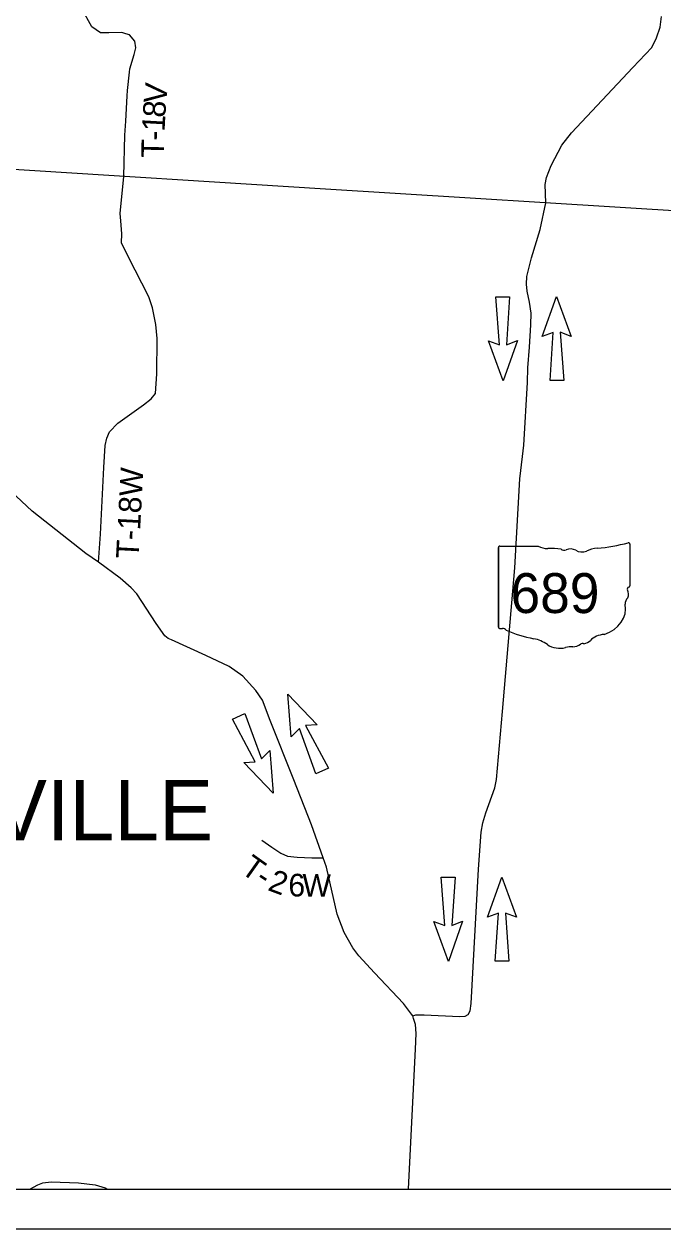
# Model space of a CAD drawing. Extents: x -15 to 405, y -40 to 87.
# Drawn here: x 25.513 to 27.116, y -34.096 to -31.075 of the extents above; entities that cross this region are included whole.
import ezdxf

# ---------------------------------------------------------------- set-up
doc = ezdxf.new("R2010")
doc.units = 0
for name, color, linetype in [('GM_P_State_Location', 7, 'Continuous'), ('GM_X_County_Road_Text', 7, 'Continuous'), ('GM_X_Minor_River', 7, 'Continuous'), ('GM_X_Rail_Line', 7, 'Continuous'), ('GM_X_State_Location', 7, 'Continuous'), ('GM_X_Township', 7, 'Continuous'), ('GM_X_Township_Subdivision', 7, 'Continuous')]:
    doc.layers.add(name, color=color, linetype=linetype)

msp = doc.modelspace()

# ---------------------------------------------------------------- linework, layer by layer
at = {"layer": 'GM_P_State_Location'}
for points in [[(25.7638, -31.4568), (25.7658, -31.3529), (25.7684, -31.3178), (25.7716, -31.2542), (25.7723, -31.2412), (25.7778, -31.195), (25.7789, -31.187), (25.7892, -31.1506), (25.7935, -31.1345), (25.7911, -31.1177), (25.778, -31.102), (25.7681, -31.0988), (25.7586, -31.096), (25.7262, -31.0966), (25.7052, -31.0963), (25.6835, -31.0815), (25.6574, -31.035)], [(25.7, -32.4234), (25.705, -32.3535), (25.7134, -32.1861), (25.7168, -32.1311), (25.7206, -32.1125), (25.7278, -32.0973), (25.7487, -32.0753), (25.8124, -32.0291), (25.8318, -32.0139), (25.8431, -32.0011), (25.8466, -31.9513), (25.8474, -31.8629), (25.844, -31.828), (25.8353, -31.7859), (25.8266, -31.7589), (25.7747, -31.6576), (25.7577, -31.623), (25.7581, -31.6003), (25.7558, -31.5676), (25.7539, -31.5494), (25.7638, -31.4568)], [(26.1098, -33.1211), (26.1352, -33.1382), (26.1575, -33.1534), (26.1738, -33.161), (26.1981, -33.1637), (26.2352, -33.1648), (26.2633, -33.1649)]]:
    msp.add_lwpolyline(points, dxfattribs=at)
at = {"layer": 'GM_X_Rail_Line'}
for p, q in [((26.2696, -31.4887), (24.8032, -31.3963)), ((27.2876, -31.5517), (26.2696, -31.4887))]:
    msp.add_line(p, q, dxfattribs=at)
at = {"layer": 'GM_X_State_Location'}
for p, q in [((26.697, -31.7584), (26.7314, -31.7581)), ((26.7062, -31.8792), (26.697, -31.7584)), ((26.7314, -31.7581), (26.7236, -31.8791)), ((26.8135, -31.8582), (26.8489, -31.7573)), ((26.8489, -31.7573), (26.8858, -31.8578)), ((26.7155, -31.9693), (26.6788, -31.8688)), ((26.6788, -31.8688), (26.7062, -31.8792)), ((26.751, -31.8684), (26.7155, -31.9693)), ((26.7236, -31.8791), (26.751, -31.8684)), ((26.841, -31.8476), (26.8135, -31.8582)), ((26.8331, -31.9685), (26.841, -31.8476)), ((26.8858, -31.8578), (26.8583, -31.8474)), ((26.8583, -31.8474), (26.8676, -31.9682)), ((26.8676, -31.9682), (26.8331, -31.9685)), ((26.1746, -32.7549), (26.249, -32.8319)), ((26.183, -32.8615), (26.1746, -32.7549)), ((26.0361, -32.8174), (26.0675, -32.8032)), ((26.0675, -32.8032), (26.1093, -32.917)), ((26.0934, -32.9241), (26.0361, -32.8174)), ((26.249, -32.8319), (26.2197, -32.8336)), ((26.2197, -32.8336), (26.277, -32.9403)), ((26.2039, -32.8407), (26.183, -32.8615)), ((26.2456, -32.9545), (26.2039, -32.8407)), ((26.1093, -32.917), (26.13, -32.8962)), ((26.13, -32.8962), (26.1383, -33.0028)), ((26.0642, -32.9257), (26.0934, -32.9241)), ((26.1383, -33.0028), (26.0642, -32.9257)), ((26.277, -32.9403), (26.2456, -32.9545)), ((26.5601, -33.214), (26.5945, -33.2139)), ((26.5688, -33.3348), (26.5601, -33.214)), ((26.5945, -33.2139), (26.5863, -33.3349)), ((26.6762, -33.3142), (26.712, -33.2135)), ((26.712, -33.2135), (26.7485, -33.3141)), ((26.7037, -33.3037), (26.6762, -33.3142)), ((26.6954, -33.4246), (26.7037, -33.3037)), ((26.7485, -33.3141), (26.7211, -33.3036)), ((26.7211, -33.3036), (26.7299, -33.4245)), ((26.5778, -33.425), (26.5415, -33.3244)), ((26.5415, -33.3244), (26.5688, -33.3348)), ((26.6137, -33.3242), (26.5778, -33.425)), ((26.5863, -33.3349), (26.6137, -33.3242)), ((26.7299, -33.4245), (26.6954, -33.4246)), ((26.4776, -33.9955), (26.4777, -33.9948))]:
    msp.add_line(p, q, dxfattribs=at)
for points in [[(26.4889, -33.5616), (26.4958, -33.559), (26.5174, -33.559), (26.6059, -33.563), (26.6203, -33.5624), (26.6276, -33.5583), (26.6326, -33.5489), (26.6348, -33.5303), (26.6535, -33.1937), (26.6598, -33.1011), (26.6643, -33.0776), (26.6719, -33.0523), (26.6948, -32.9892), (26.6989, -32.9684), (26.7136, -32.7984), (26.7447, -32.4384), (26.7575, -32.2149), (26.7641, -32.1587), (26.7668, -32.1303), (26.7767, -31.9735), (26.7776, -31.9363), (26.7814, -31.8851), (26.7849, -31.8289), (26.7857, -31.7993), (26.7812, -31.7715), (26.7755, -31.7441), (26.7735, -31.727), (26.7745, -31.7072), (26.7866, -31.6611), (26.8085, -31.5896), (26.8228, -31.5229), (26.8205, -31.4766), (26.8237, -31.4592), (26.836, -31.429), (26.8625, -31.3785), (26.8865, -31.3473), (27.0404, -31.1836), (27.0883, -31.1334), (27.1004, -31.1089), (27.1095, -31.0821), (27.113, -31.0559)], [(26.4889, -33.5616), (26.4856, -33.5573), (26.4651, -33.5304), (26.3922, -33.4538), (26.3533, -33.4106), (26.338, -33.391), (26.3166, -33.3527), (26.2991, -33.3061), (26.2716, -33.1887), (26.2633, -33.1649), (26.2344, -33.0822), (26.1897, -32.9698), (26.1308, -32.8204), (26.1114, -32.7696), (26.0951, -32.7454), (26.0622, -32.7096), (26.028, -32.6851), (25.9692, -32.6577), (25.8832, -32.6187), (25.8745, -32.6148), (25.8666, -32.6082), (25.8443, -32.5775), (25.796, -32.5035), (25.7822, -32.4884), (25.7545, -32.4637), (25.7, -32.4234), (25.6684, -32.402), (25.5337, -32.2959), (25.4801, -32.2457)], [(26.4777, -33.9948), (26.4953, -33.6452), (26.497, -33.6054), (26.4951, -33.5826), (26.4907, -33.5681), (26.4889, -33.5616)], [(25.5276, -33.9955), (25.5474, -33.9853), (25.5601, -33.9802), (25.5814, -33.9771), (25.65, -33.98), (25.6917, -33.9852), (25.7163, -33.9928), (25.7223, -33.9955)]]:
    msp.add_lwpolyline(points, dxfattribs=at)
at = {"layer": 'GM_X_Township'}
for p, q in [((23.1652, -33.9955), (29.9652, -33.9955)), ((23.0652, -34.0955), (30.0652, -34.0955))]:
    msp.add_line(p, q, dxfattribs=at)
at = {"layer": 'GM_X_Township_Subdivision'}
for p, q in [((27.0331, -32.3785), (27.0331, -32.4832)), ((26.7035, -32.3869), (26.7035, -32.587)), ((26.7035, -32.587), (26.7035, -32.3869)), ((26.7035, -32.587), (26.7035, -32.3869)), ((26.7068, -32.3834), (26.8033, -32.3834)), ((27.0331, -32.4831), (27.0331, -32.4832))]:
    msp.add_line(p, q, dxfattribs=at)
for centre, major_axis, start_param, end_param in [((26.9157, -32.1106), (0.3495, 0), 4.814394, 5.042369), ((27.0295, -32.378), (0.00367, 0), 6.141152, 7.989035), ((26.7073, -32.3865), (0.00382, 0), 1.712693, 3.28349), ((26.8263, -32.3602), (0.037, 0), 4.042523, 4.731795), ((26.8386, -32.4958), (0.133, 0), 1.404758, 1.657858), ((26.8687, -32.3854), (0.0107, 0), 3.836095, 5.185415), ((26.8844, -32.4085), (0.0222, 0), 0.950623, 2.079405), ((26.9131, -32.3768), (0.0267, 0), 4.081561, 5.145723), ((26.9603, -32.4446), (0.0703, 0), 1.699011, 2.107814), ((27.0323, -32.4908), (0.00568, 0), 1.883978, 3.671073), ((26.9961, -32.5041), (0.0341, 0), 5.934695, 6.695948), ((27.0292, -32.4836), (0.00393, 0), 5.05454, 6.418171), ((26.9353, -32.5403), (0.0874, 0), 5.101752, 6.440018), ((27.0463, -32.527), (0.0248, 0), 2.387724, 3.262537), ((26.7073, -32.5874), (0.00385, 0), 3.00124, 4.508301), ((26.7079, -32.567), (0.0294, 0), 4.665946, 4.897461), ((26.7139, -32.5985), (0.0106, 0), 0.519207, 1.627899), ((26.8478, -32.4187), (0.2524, 0), 4.195997, 4.488961), ((26.7725, -32.6769), (0.079, 0), 0.823519, 1.323587), ((26.9115, -32.6064), (0.0282, 0), 4.937069, 5.64225), ((26.9721, -32.6432), (0.0479, 0), 1.647645, 2.488434), ((26.8579, -32.5995), (0.0501, 0), 4.026481, 4.996735), ((26.8869, -32.6687), (0.0412, 0), 1.495662, 1.94098), ((26.8905, -32.6145), (0.0267, 0), 4.691044, 5.507374), ((26.9147, -32.6339), (0.00752, 0), 1.147584, 2.315152)]:
    msp.add_ellipse(centre, major_axis=major_axis, ratio=0.8, start_param=start_param, end_param=end_param, dxfattribs=at)

# ---------------------------------------------------------------- texts
at = {"layer": 'GM_X_County_Road_Text'}
msp.add_text('WILKESVILLE', height=0.151515, rotation=0, dxfattribs=at).set_placement((24.6697, -33.1212))
at = {"layer": 'GM_X_Minor_River'}
for s, height, rotation, p in [('V', 0.0568, 84.7178, (25.8696, -31.2756)), ('8', 0.0568, 86.4487, (25.8674, -31.3101)), ('1', 0.0568, 86.8239, (25.8655, -31.345)), ('-', 0.0568, 87.8919, (25.8647, -31.368)), ('T', 0.0568, 88.9457, (25.8639, -31.4102)), ('T-18W', 0.05682, 86.9118, (25.8004, -32.4161)), ('T', 0.0568, 324.6611, (26.0538, -33.2006)), ('2', 0.0568, 339.3877, (26.1221, -33.2454)), ('-', 0.0568, 326.8266, (26.0904, -33.2265)), ('6', 0.0568, 359.3875, (26.176, -33.2617)), ('W', 0.0568, 359.2641, (26.2109, -33.2621))]:
    msp.add_text(s, height=height, rotation=rotation, dxfattribs=at).set_placement(p)
at = {"layer": 'GM_X_Township_Subdivision'}
msp.add_text('689', height=0.1, dxfattribs=at).set_placement((26.7338, -32.5513))

doc.saveas('drawing.dxf')
